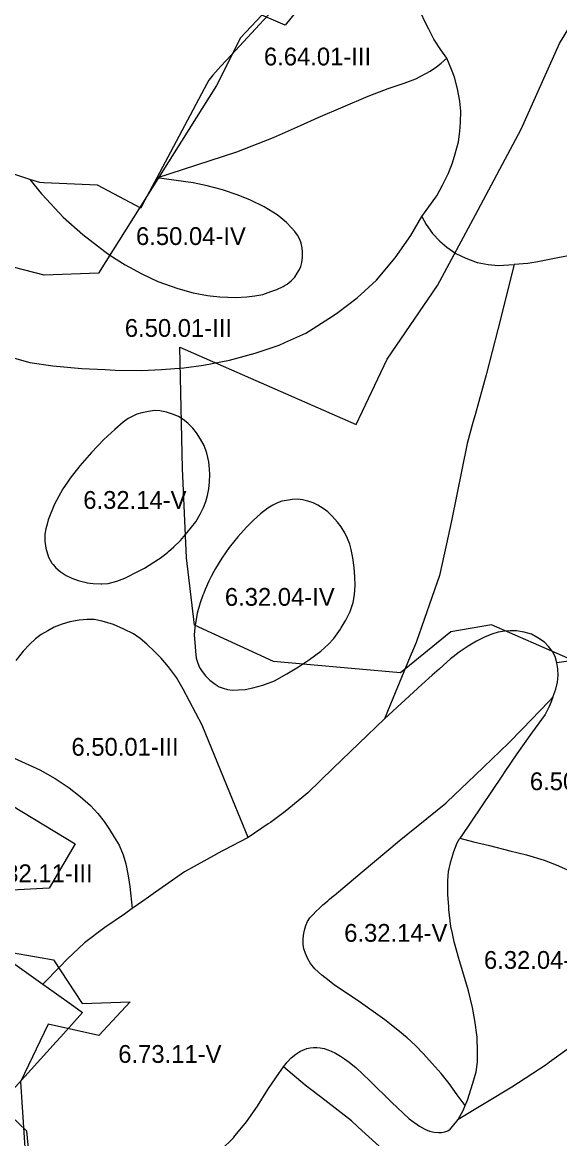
# Model space of a CAD drawing. Extents: x -555156 to -540209, y -1046851 to -1035695.
# Drawn here: x -544298 to -543996, y -1039781 to -1039153 of the extents above; entities that cross this region are included whole.
import ezdxf

# ---------------------------------------------------------------- set-up
doc = ezdxf.new("R2010")
doc.units = 0
for name, color, linetype in [('Vrstva 27', 7, 'Continuous'), ('Vrstva 28', 7, 'Continuous'), ('Vrstva 29', 7, 'Continuous')]:
    doc.layers.add(name, color=color, linetype=linetype)

msp = doc.modelspace()

# ---------------------------------------------------------------- linework, layer by layer
at = {"layer": 'Vrstva 28'}
for points in [[(-544119.25, -1039106.05), (-544124.02, -1039117.06), (-544130.73, -1039131.72), (-544131.85, -1039134.17), (-544132.45, -1039135.48), (-544136.77, -1039135.78), (-544146.78, -1039134.88), (-544180.61, -1039171.66), (-544186.58, -1039178.15), (-544191.24, -1039183.22), (-544193.36, -1039186.09), (-544195.93, -1039190.9), (-544211.71, -1039220.48), (-544222.58, -1039240.86)], [(-544059.74, -1039173.58), (-544063.09, -1039168.88), (-544066.98, -1039162.9), (-544069.81, -1039157.37), (-544072.35, -1039152.29), (-544074.96, -1039146.31), (-544075.49, -1039145.11), (-544076.65, -1039142.57), (-544077.88, -1039139.88), (-544079.97, -1039134.2)], [(-544222.58, -1039240.86), (-544177.67, -1039226.29), (-544157.02, -1039218.18), (-544146.94, -1039213.66), (-544141.89, -1039211.4), (-544131.93, -1039206.94), (-544103.81, -1039195.06), (-544092.6, -1039190.72), (-544083.64, -1039187.73), (-544077.07, -1039185.19), (-544069, -1039181.01), (-544065.55, -1039178.53), (-544062.9, -1039176.4), (-544059.74, -1039173.58)], [(-544073.79, -1039262.73), (-544065.83, -1039251.84), (-544065.37, -1039251.02), (-544063.64, -1039247.89), (-544062.09, -1039245.11), (-544058.81, -1039238.24), (-544056.57, -1039232.56), (-544054.92, -1039227.33), (-544053.13, -1039220.6), (-544052.38, -1039214.78), (-544051.94, -1039209.55), (-544051.79, -1039203.42), (-544052.38, -1039197.74), (-544053.73, -1039190.86), (-544055.37, -1039184.29), (-544057.01, -1039179.95), (-544059.74, -1039173.58)], [(-544293.9, -1039241.79), (-544324.11, -1039231.9)], [(-544222.58, -1039240.86), (-544230.61, -1039255.92), (-544231.69, -1039258.01), (-544255.89, -1039244.95), (-544286.03, -1039243.69), (-544288.41, -1039243.59), (-544293.9, -1039241.79)], [(-544293.9, -1039241.79), (-544287.48, -1039249.84), (-544287.1, -1039250.32), (-544275.15, -1039263.03), (-544264.25, -1039272.74), (-544251.92, -1039282.37), (-544248.94, -1039284.31), (-544240.48, -1039289.8), (-544231.01, -1039294.84), (-544222.13, -1039299.11), (-544210.86, -1039303.12), (-544202.16, -1039305.6), (-544194.22, -1039307.05), (-544192.56, -1039307.23), (-544188.87, -1039307.64), (-544187.22, -1039307.82), (-544178.26, -1039308.24), (-544172.03, -1039307.73), (-544167.5, -1039307.3), (-544163.09, -1039306.58), (-544158.51, -1039304.87), (-544155.14, -1039303.6), (-544151.58, -1039301.94), (-544150.45, -1039301.25), (-544149.43, -1039300.63), (-544147.14, -1039298.87), (-544145.14, -1039296.67), (-544143.73, -1039294.57), (-544142.51, -1039292.38), (-544141.78, -1039290.67), (-544141.14, -1039288.47), (-544140.74, -1039285.61), (-544140.69, -1039282.78), (-544140.89, -1039280.34), (-544141.47, -1039277.65), (-544142.35, -1039275.51), (-544143.67, -1039273.21), (-544145.08, -1039271.11), (-544147.03, -1039268.97), (-544149.79, -1039266.01), (-544155.08, -1039261.74), (-544162.25, -1039257.3)], [(-544162.25, -1039257.3), (-544170.01, -1039253.46), (-544177.01, -1039250.56), (-544185.63, -1039247.74), (-544194.34, -1039245.35), (-544202.28, -1039243.81), (-544222.58, -1039240.86)], [(-544099.25, -1039298.35), (-544088.8, -1039285.95), (-544079.99, -1039273.39), (-544073.79, -1039262.73)], [(-544073.79, -1039262.73), (-544071.25, -1039267.07), (-544067.67, -1039272.15), (-544063.63, -1039276.48), (-544059.75, -1039279.92), (-544054.67, -1039283.36), (-544048.99, -1039286.05), (-544042.72, -1039288.44), (-544036.45, -1039289.63), (-544030.88, -1039290.12), (-544021.92, -1039289.67)], [(-544021.92, -1039289.67), (-544030.96, -1039326.21), (-544037.33, -1039350.91), (-544037.5, -1039351.58), (-544043.81, -1039374.1), (-544045.04, -1039378.47), (-544048.35, -1039390.29), (-544057.04, -1039433.77), (-544059.94, -1039446.74), (-544063.9, -1039464.43), (-544076.71, -1039501.51), (-544076.98, -1039502.17), (-544078.42, -1039505.65), (-544080.28, -1039510.11), (-544090.06, -1039533.62), (-544094.78, -1039544.99)], [(-543991.6, -1039284.74), (-544000.11, -1039286.38), (-544008.63, -1039288.17), (-544014.15, -1039289.07), (-544021.92, -1039289.67)], [(-544312.4, -1039339.15), (-544303.89, -1039341.99), (-544294.03, -1039344.68), (-544281.04, -1039346.62), (-544264.75, -1039348.12), (-544251.55, -1039348.76), (-544246.08, -1039349.02), (-544231.3, -1039349.32), (-544219.94, -1039348.72), (-544207.4, -1039347.67), (-544196.34, -1039346.18), (-544181.71, -1039343.49), (-544167.37, -1039339.45), (-544154.53, -1039335.17), (-544153.92, -1039334.97), (-544150.63, -1039333.5), (-544138.84, -1039328.24), (-544123.9, -1039318.68), (-544121.01, -1039316.53), (-544110.01, -1039308.37), (-544099.25, -1039298.35)], [(-544253.59, -1039469.16), (-544250.04, -1039469.01), (-544245, -1039467.65), (-544240.65, -1039466.02), (-544238.39, -1039464.88), (-544234.76, -1039463.04), (-544229.55, -1039460.3), (-544221.62, -1039455.35), (-544220.78, -1039454.72), (-544216.53, -1039451.49), (-544215.98, -1039451.08), (-544213.13, -1039448.38), (-544209.41, -1039444.85), (-544205.48, -1039440.4), (-544200.79, -1039434.34), (-544198.18, -1039430.03), (-544196.43, -1039426.27), (-544195.16, -1039422.96), (-544194.18, -1039419.54), (-544193.45, -1039415.68), (-544192.97, -1039411.78), (-544192.82, -1039407.78), (-544193.04, -1039404.75), (-544193.38, -1039400.61), (-544194.6, -1039395.63), (-544196.11, -1039391.43), (-544198.11, -1039387.77), (-544200.25, -1039384.31), (-544202.4, -1039381.57), (-544205.28, -1039378.84), (-544207.86, -1039376.84), (-544210.5, -1039375.18), (-544213.86, -1039373.72), (-544217.13, -1039372.59), (-544220.84, -1039371.86), (-544223.96, -1039371.81), (-544227.23, -1039372.2), (-544231.03, -1039372.94), (-544233.91, -1039373.77), (-544236.1, -1039374.84), (-544238.64, -1039376.25), (-544241.46, -1039378.33), (-544246.16, -1039382.34), (-544252.39, -1039388.06), (-544259.39, -1039395.32), (-544265.96, -1039402.84), (-544271.34, -1039409.84), (-544273.24, -1039412.6), (-544275.36, -1039415.68), (-544275.69, -1039416.16), (-544280.13, -1039424.36), (-544283.63, -1039433.24), (-544284.27, -1039435.54), (-544284.95, -1039438.18), (-544285.63, -1039441.26), (-544285.63, -1039445.1), (-544284.95, -1039449.2), (-544283.5, -1039454.15), (-544281.53, -1039457.48), (-544280.9, -1039458.23), (-544279.32, -1039460.13), (-544277.01, -1039462.18), (-544273.51, -1039464.4), (-544270.44, -1039466.02), (-544266.77, -1039467.39), (-544263.01, -1039468.33), (-544261.67, -1039468.53), (-544258.4, -1039469.01)], [(-544176.69, -1039528.82), (-544173.08, -1039528.57), (-544168.73, -1039527.72), (-544163.09, -1039526.1), (-544156.52, -1039523.62), (-544149.61, -1039519.78), (-544142.95, -1039515.85), (-544136.8, -1039511.66), (-544130.49, -1039506.97), (-544126.31, -1039503.3), (-544123.09, -1039499.88), (-544119.42, -1039494.58), (-544119.03, -1039493.94), (-544117.35, -1039491.16), (-544116.43, -1039489.63), (-544115.49, -1039487.67), (-544114.04, -1039484.68), (-544112.34, -1039479.64), (-544111.48, -1039475.28), (-544111.14, -1039469.9), (-544111.31, -1039465.46), (-544111.74, -1039459.91), (-544112.59, -1039454.53), (-544113.49, -1039449.85), (-544114.27, -1039446.92), (-544115.49, -1039443.65), (-544116.9, -1039440.48), (-544119.05, -1039437.21), (-544121.2, -1039434.43), (-544124.03, -1039431.16), (-544126.61, -1039428.72), (-544129.15, -1039426.86), (-544132.07, -1039425.01), (-544134.8, -1039423.64), (-544137.73, -1039422.62), (-544140.71, -1039421.94), (-544143.44, -1039421.64), (-544146.51, -1039421.69), (-544149.73, -1039422.23), (-544152.36, -1039422.76), (-544154.8, -1039423.69), (-544157.48, -1039424.86), (-544160.27, -1039426.64), (-544164.28, -1039429.79), (-544168.38, -1039433.47), (-544172.22, -1039437.31), (-544177.08, -1039442.78), (-544181.95, -1039448.84), (-544186.17, -1039454.67), (-544189.63, -1039460.52), (-544190.61, -1039462.18), (-544192.06, -1039465.09), (-544193.34, -1039467.65)], [(-544258.4, -1039469.01), (-544254.05, -1039469.18), (-544253.59, -1039469.16)], [(-544193.34, -1039467.65), (-544195.39, -1039472.41), (-544196.25, -1039474.39), (-544196.68, -1039475.56), (-544198.21, -1039479.78), (-544200, -1039485.67), (-544201.35, -1039493.78), (-544201.56, -1039497.78), (-544201.27, -1039502.08), (-544200.88, -1039506.96), (-544200.44, -1039510.91), (-544199.66, -1039513.84), (-544198.69, -1039516.13), (-544197.08, -1039518.47), (-544195.27, -1039520.91), (-544192.83, -1039523.35), (-544189.91, -1039525.65), (-544187.52, -1039527.01), (-544185.27, -1039527.84), (-544182.93, -1039528.52), (-544180.05, -1039528.91), (-544176.69, -1039528.82)], [(-544171.25, -1039611.73), (-544179.84, -1039590.75), (-544197.1, -1039548.6), (-544207.8, -1039528.33), (-544211.64, -1039521.75), (-544215.99, -1039515.86), (-544220.26, -1039510.99), (-544223.85, -1039507.24), (-544228.2, -1039503.05), (-544231.96, -1039499.98), (-544235.8, -1039497.24), (-544241.09, -1039494.6), (-544246.98, -1039492.12), (-544253.29, -1039490.16), (-544257.73, -1039489.22), (-544261.83, -1039489.22), (-544266.27, -1039489.56), (-544271.56, -1039490.58), (-544275.83, -1039491.78), (-544280.27, -1039493.57), (-544283.85, -1039495.54), (-544287.69, -1039497.67), (-544290.76, -1039500.15), (-544294.09, -1039503.31), (-544297.76, -1039507.07), (-544301.86, -1039512.19)], [(-543997.85, -1039513.61), (-543998.87, -1039510.11), (-544000.41, -1039507.2), (-544002.54, -1039504.38), (-544004.85, -1039501.91), (-544008.52, -1039499.52), (-544012.19, -1039497.55), (-544016.2, -1039496.36), (-544020.55, -1039495.67), (-544024.14, -1039495.67), (-544027.12, -1039495.76), (-544030.79, -1039496.36), (-544034.38, -1039497.47), (-544038.56, -1039499.18), (-544043.09, -1039501.48), (-544047.78, -1039504.13), (-544052.73, -1039507.54), (-544056.07, -1039510.13), (-544057.64, -1039511.35), (-544059.45, -1039512.98), (-544064, -1039517.07), (-544067.94, -1039520.61), (-544073.68, -1039525.82), (-544094.78, -1039544.99)], [(-544000.07, -1039532.91), (-543999.53, -1039531.36), (-543998.53, -1039528.47), (-543997.59, -1039524.54), (-543997.17, -1039520.78), (-543997.25, -1039516.94), (-543997.85, -1039513.61)], [(-543953.85, -1039640.58), (-543951.61, -1039626.54), (-543947.69, -1039602.74), (-543945.9, -1039587.49), (-543944.56, -1039572.25), (-543944.41, -1039562.81), (-543944.33, -1039557.66), (-543944.26, -1039553.05), (-543944.18, -1039548.04), (-543944.7, -1039540.01), (-543945.29, -1039535.4), (-543946.57, -1039530.87), (-543948.28, -1039527.03), (-543950.24, -1039523.87), (-543953.06, -1039520.71), (-543955.96, -1039518.4), (-543959.46, -1039516.1), (-543962.96, -1039514.3), (-543967.06, -1039512.77), (-543971.84, -1039511.83), (-543978.07, -1039511.32), (-543984.9, -1039511.66), (-543997.85, -1039513.61)], [(-544077.23, -1039728.68), (-544082.01, -1039724.41), (-544087.13, -1039720.14), (-544094.56, -1039714.29), (-544109.5, -1039703.61), (-544122.73, -1039694.9), (-544125.87, -1039692.46), (-544129.98, -1039689.26), (-544133.91, -1039685.68), (-544136.28, -1039682.63), (-544137.89, -1039679.7), (-544139.1, -1039676.97), (-544140.03, -1039674.43), (-544140.42, -1039671.95), (-544140.37, -1039669.16), (-544140.13, -1039666.77), (-544139.59, -1039663.89), (-544138.91, -1039661.26), (-544137.93, -1039659.06), (-544136.57, -1039657.01), (-544135.01, -1039655.21), (-544133.06, -1039653.3), (-544131.4, -1039651.74), (-544129.3, -1039649.74), (-544127.59, -1039648.33), (-544126.56, -1039647.37), (-544125.64, -1039646.52), (-544123.34, -1039644.59), (-544123.03, -1039644.33), (-544107.26, -1039631.15), (-544086.43, -1039613.74), (-544060.29, -1039592.55), (-544059.65, -1039591.94), (-544043.78, -1039576.76), (-544025.01, -1039558.81), (-544017.23, -1039550.73), (-544007.49, -1039540.62), (-544002.25, -1039535.17), (-544000.07, -1039532.91)], [(-544000.07, -1039532.91), (-544001.13, -1039535.6), (-544002.12, -1039538.12), (-544004.08, -1039541.82), (-544004.51, -1039542.64), (-544012.14, -1039553.05), (-544020.27, -1039564.82), (-544027.03, -1039574.6), (-544028.87, -1039577.26), (-544051.72, -1039611.19), (-544052.34, -1039612.26)], [(-544094.78, -1039544.99), (-544123.61, -1039572.79), (-544137.8, -1039586.69), (-544141.16, -1039589.46), (-544150.5, -1039597.15), (-544158.71, -1039603.28), (-544159.99, -1039604.14), (-544171.25, -1039611.73)], [(-544302.75, -1039567.15), (-544288.32, -1039573.75), (-544279.66, -1039578.68), (-544271.89, -1039583.91), (-544265.62, -1039588.69), (-544259.85, -1039593.78), (-544255.76, -1039598.3), (-544252.26, -1039602.83), (-544249.27, -1039607.27), (-544246.54, -1039611.54), (-544243.81, -1039616.15), (-544241.5, -1039621.45), (-544240.12, -1039626.65), (-544238.84, -1039632.38), (-544238.49, -1039634.54)], [(-544443.71, -1039598.18), (-544453.98, -1039626.34), (-544384.32, -1039646.27), (-544318.42, -1039674.46), (-544303.72, -1039682.01), (-544286.59, -1039694.27)], [(-544171.25, -1039611.73), (-544184.88, -1039618.95), (-544188.9, -1039621.07), (-544189.03, -1039621.14), (-544201.64, -1039628.09), (-544207.06, -1039631.08), (-544223.4, -1039642.61), (-544227.31, -1039645.37), (-544230.51, -1039647.63)], [(-544048.06, -1039759.4), (-544045.08, -1039749.98), (-544043.28, -1039743.55), (-544042.39, -1039738.02), (-544042.39, -1039731.3), (-544042.66, -1039724.84), (-544042.69, -1039724.13), (-544044.03, -1039714.71), (-544045.22, -1039707.39), (-544047.57, -1039698.09), (-544052.95, -1039679.86), (-544055.48, -1039670.44), (-544056.51, -1039665.85), (-544057.43, -1039661.76), (-544058.47, -1039652.36), (-544058.58, -1039650.73), (-544059.07, -1039643.84), (-544059.07, -1039636.22), (-544058.77, -1039630.84), (-544057.43, -1039625.31), (-544055.78, -1039619.63), (-544053.84, -1039614.85), (-544052.34, -1039612.26)], [(-544052.34, -1039612.26), (-544044.67, -1039614.28), (-544035.71, -1039616.37), (-544024.36, -1039619.21), (-544014.95, -1039621.6), (-544005.09, -1039624.59), (-543998.22, -1039627.13), (-543991.94, -1039629.97), (-543984.92, -1039633.56), (-543978.8, -1039637.15), (-543972.97, -1039641.33), (-543957.44, -1039656.13)], [(-544238.49, -1039634.54), (-544237.73, -1039639.29), (-544236.41, -1039651.8)], [(-544230.51, -1039647.63), (-544236.41, -1039651.8)], [(-544236.41, -1039651.8), (-544240.78, -1039654.88), (-544251.76, -1039662.47), (-544263.26, -1039671.1), (-544272.93, -1039680.25), (-544276.98, -1039684.41), (-544286.59, -1039694.27)], [(-544286.59, -1039694.27), (-544280.35, -1039698.73), (-544269.21, -1039706.69), (-544264.36, -1039710.16), (-544265.92, -1039711.95), (-544276.58, -1039723.86), (-544279.1, -1039726.68), (-544302, -1039751.89), (-544311.24, -1039762.06), (-544304.47, -1039768.49), (-544295.86, -1039776.66), (-544291.48, -1039821.68), (-544288.66, -1039833.78), (-544281.17, -1039865.86), (-544284.72, -1039871.32), (-544291.97, -1039882.48)], [(-544151.53, -1039740.66), (-544149.39, -1039738.12), (-544147.15, -1039735.73), (-544144.46, -1039733.63), (-544142.22, -1039732.12), (-544140.17, -1039731.14), (-544138.71, -1039730.62), (-544138.27, -1039730.46), (-544136.46, -1039730.07), (-544134.61, -1039729.87), (-544132.66, -1039729.87), (-544130.81, -1039730.02), (-544128.56, -1039730.46), (-544126.47, -1039731.09), (-544124.61, -1039731.92), (-544122.17, -1039733.14), (-544119.49, -1039734.65), (-544117.15, -1039736.21), (-544114.56, -1039738.17), (-544112.47, -1039739.83), (-544110.73, -1039741.19), (-544102.88, -1039748.53), (-544090.76, -1039760.66), (-544080.86, -1039769.97), (-544075.06, -1039774.17), (-544071.99, -1039775.87), (-544070.82, -1039776.36), (-544069.4, -1039776.95), (-544066.72, -1039777.53), (-544064.28, -1039777.68), (-544062.62, -1039777.63), (-544060.87, -1039777.34), (-544059.21, -1039776.75), (-544057.84, -1039775.78), (-544056.43, -1039774.34), (-544053.29, -1039770.31)], [(-544049.32, -1039762.55), (-544053.85, -1039756.43), (-544058.46, -1039750.03), (-544062.89, -1039744.39), (-544068.01, -1039738.84), (-544072.71, -1039733.46), (-544077.23, -1039728.68)], [(-543987.26, -1039727.56), (-543992.02, -1039731.01), (-544002.07, -1039738.17), (-544003.97, -1039739.53), (-544023.08, -1039752.24)], [(-544201.25, -1039798.25), (-544194.18, -1039793.24), (-544192.31, -1039791.91), (-544186.48, -1039787.42), (-544179.61, -1039780.7), (-544178.71, -1039779.6), (-544176.7, -1039777.14), (-544172.29, -1039771.73), (-544166.02, -1039762.76), (-544160.19, -1039753.5), (-544155.72, -1039746.92), (-544154.02, -1039744.41), (-544152.79, -1039742.56), (-544151.53, -1039740.66)], [(-544073.71, -1039807.24), (-544076.78, -1039804.44), (-544093.62, -1039789.07), (-544109.46, -1039774.6), (-544113.22, -1039771.17), (-544128.27, -1039759.4), (-544139.32, -1039751.03), (-544151.53, -1039740.66)], [(-544023.08, -1039752.24), (-544053.29, -1039770.31)], [(-544049.32, -1039762.55), (-544048.06, -1039759.4)], [(-544053.29, -1039770.31), (-544050.45, -1039765.37), (-544049.32, -1039762.55)]]:
    msp.add_lwpolyline(points, dxfattribs=at)
at = {"layer": 'Vrstva 29'}
for points in [[(-544122.156006, -1039120.041016), (-544150.562988, -1039155.025024), (-544163.66395, -1039149.410941), (-544175.648169, -1039162.23008), (-544189.096985, -1039189.031006), (-544255.461975, -1039294.53302), (-544285.979004, -1039295.661011), (-544320.130005, -1039286.750977)], [(-543991.619995, -1039510.997986), (-544034.541992, -1039492.315979), (-544057.403992, -1039496.223999), (-544085.682007, -1039519.237976), (-544121.65802, -1039516.015015), (-544157.127014, -1039512.840027), (-544201.421997, -1039492.494995), (-544205.951904, -1039454.580994), (-544208.278992, -1039404.386902), (-544209.640015, -1039336.185913), (-544110.588013, -1039379.671021), (-544093.247009, -1039342.851013), (-544064.992004, -1039301.479004), (-544043.537903, -1039261.742004), (-544017.942993, -1039213.484009), (-543996.447021, -1039165.338989), (-543975.200989, -1039130.426025)], [(-544303.689026, -1039594.016907), (-544268.426025, -1039615.271912), (-544283.10498, -1039640.367004), (-544346.286011, -1039643.690979)], [(-544315.06, -1039674.66), (-544280.66, -1039680.59), (-544264.57, -1039705.09), (-544237.59, -1039704.1), (-544255.11, -1039723.07), (-544283.69, -1039716.79), (-544299.3, -1039749.2), (-544296.18, -1039794.66)]]:
    msp.add_lwpolyline(points, dxfattribs=at)

# ---------------------------------------------------------------- texts
at = {"layer": 'Vrstva 27'}
for s, p in [('6.64.01-III', (-544162.436548, -1039177.7)), ('6.50.04-IV', (-544234.297119, -1039278.67)), ('6.50.01-III', (-544240.606548, -1039330.31)), ('6.32.14-V', (-544263.940884, -1039427.01)), ('6.32.04-IV', (-544184.387119, -1039481.51)), ('6.50.01-III', (-544270.586548, -1039565.81)), ('6.50.04-IV', (-544013.037119, -1039585.18)), ('6.32.11-III', (-544318.896548, -1039636.92)), ('6.32.14-V', (-544117.350884, -1039670.43)), ('6.32.04-IV', (-544038.827119, -1039685.64)), ('6.73.11-V', (-544244.281006, -1039738.49))]:
    msp.add_text(s, height=10, dxfattribs=at).set_placement(p)

doc.saveas('drawing.dxf')
